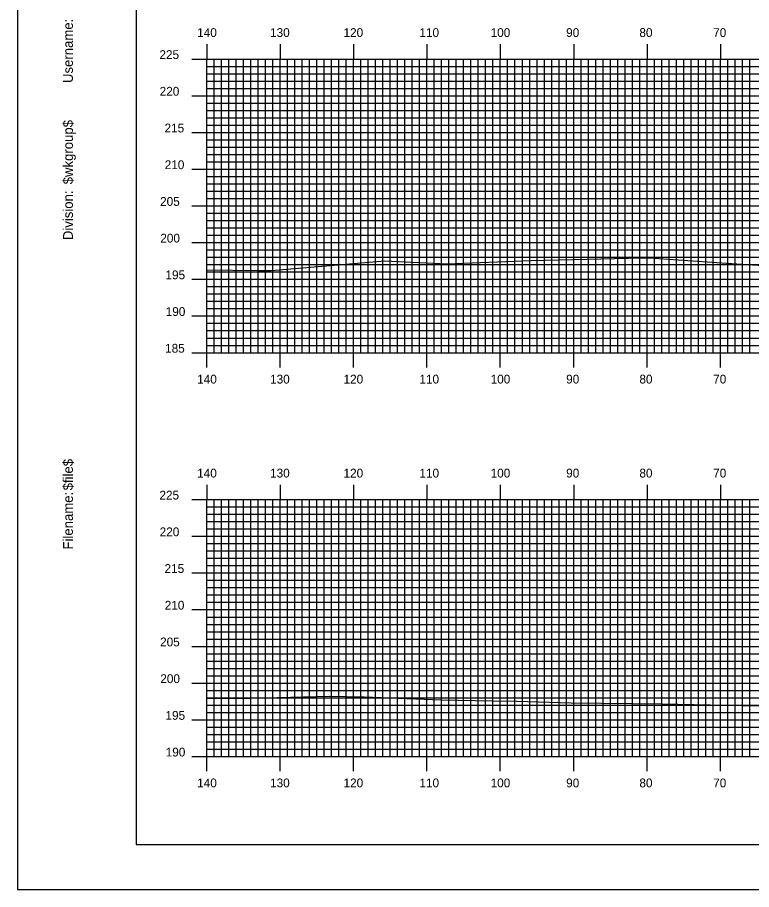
# Model space of a CAD drawing. Extents: x 1812161 to 1812504, y 442591 to 442811.
# Drawn here: x 1812160.6 to 1812260.7, y 442590.5 to 442709.3 of the extents above; entities that cross this region are included whole.
import ezdxf

# ---------------------------------------------------------------- set-up
doc = ezdxf.new("R2010")
doc.units = 0
for name, color, linetype in [('BORDER', 7, 'Continuous'), ('H_V ANNOTATION', 7, 'Continuous'), ('MAJOR', 7, 'Continuous'), ('MINOR', 7, 'Continuous'), ('PLOT BOUNDARY', 7, 'Continuous'), ('S_Roadway_Centerline', 7, 'Continuous')]:
    doc.layers.add(name, color=color, linetype=linetype)

msp = doc.modelspace()

# ---------------------------------------------------------------- linework, layer by layer
at = {"layer": 'BORDER'}
msp.add_lwpolyline([(1812176.83, 442596.67), (1812496.83, 442596.67), (1812496.83, 442806.67), (1812176.83, 442806.67)], close=True, dxfattribs=at)
at = {"layer": 'MAJOR'}
for p, q in [((1812186.43, 442705.67), (1812186.43, 442703.67)), ((1812196.43, 442705.67), (1812196.43, 442703.67)), ((1812206.43, 442705.67), (1812206.43, 442703.67)), ((1812216.43, 442705.67), (1812216.43, 442703.67)), ((1812226.43, 442705.67), (1812226.43, 442703.67)), ((1812236.43, 442705.67), (1812236.43, 442703.67)), ((1812246.43, 442705.67), (1812246.43, 442703.67)), ((1812256.43, 442705.67), (1812256.43, 442703.67)), ((1812184.42, 442703.67), (1812186.43, 442703.67)), ((1812186.43, 442703.67), (1812466.43, 442703.67)), ((1812186.43, 442663.67), (1812186.43, 442703.67)), ((1812186.43, 442663.67), (1812186.43, 442703.67)), ((1812186.43, 442703.67), (1812466.43, 442703.67)), ((1812196.43, 442663.67), (1812196.43, 442703.67)), ((1812206.43, 442663.67), (1812206.43, 442703.67)), ((1812216.43, 442663.67), (1812216.43, 442703.67)), ((1812226.43, 442663.67), (1812226.43, 442703.67)), ((1812236.43, 442663.67), (1812236.43, 442703.67)), ((1812246.43, 442663.67), (1812246.43, 442703.67)), ((1812256.43, 442663.67), (1812256.43, 442703.67)), ((1812184.42, 442698.67), (1812186.43, 442698.67)), ((1812186.43, 442698.67), (1812466.43, 442698.67)), ((1812184.42, 442693.67), (1812186.43, 442693.67)), ((1812186.43, 442693.67), (1812466.43, 442693.67)), ((1812184.42, 442688.67), (1812186.43, 442688.67)), ((1812186.43, 442688.67), (1812466.43, 442688.67)), ((1812184.42, 442683.67), (1812186.43, 442683.67)), ((1812186.43, 442683.67), (1812466.43, 442683.67)), ((1812184.42, 442678.67), (1812186.43, 442678.67)), ((1812186.43, 442678.67), (1812466.43, 442678.67)), ((1812184.42, 442673.67), (1812186.43, 442673.67)), ((1812186.43, 442673.67), (1812466.43, 442673.67)), ((1812184.42, 442668.67), (1812186.43, 442668.67)), ((1812186.43, 442668.67), (1812466.43, 442668.67)), ((1812184.42, 442663.67), (1812186.43, 442663.67)), ((1812186.43, 442663.67), (1812466.43, 442663.67)), ((1812186.43, 442663.67), (1812466.43, 442663.67)), ((1812186.43, 442661.66), (1812186.43, 442663.67)), ((1812196.43, 442661.66), (1812196.43, 442663.67)), ((1812206.43, 442661.66), (1812206.43, 442663.67)), ((1812216.43, 442661.66), (1812216.43, 442663.67)), ((1812226.43, 442661.66), (1812226.43, 442663.67)), ((1812236.43, 442661.66), (1812236.43, 442663.67)), ((1812246.43, 442661.66), (1812246.43, 442663.67)), ((1812256.43, 442661.66), (1812256.43, 442663.67)), ((1812186.43, 442645.67), (1812186.43, 442643.67)), ((1812196.43, 442645.67), (1812196.43, 442643.67)), ((1812206.43, 442645.67), (1812206.43, 442643.67)), ((1812216.43, 442645.67), (1812216.43, 442643.67)), ((1812226.43, 442645.67), (1812226.43, 442643.67)), ((1812236.43, 442645.67), (1812236.43, 442643.67)), ((1812246.43, 442645.67), (1812246.43, 442643.67)), ((1812256.43, 442645.67), (1812256.43, 442643.67)), ((1812184.42, 442643.67), (1812186.43, 442643.67)), ((1812186.43, 442643.67), (1812466.43, 442643.67)), ((1812186.43, 442608.67), (1812186.43, 442643.67)), ((1812186.43, 442608.67), (1812186.43, 442643.67)), ((1812186.43, 442643.67), (1812466.43, 442643.67)), ((1812196.43, 442608.67), (1812196.43, 442643.67)), ((1812206.43, 442608.67), (1812206.43, 442643.67)), ((1812216.43, 442608.67), (1812216.43, 442643.67)), ((1812226.43, 442608.67), (1812226.43, 442643.67)), ((1812236.43, 442608.67), (1812236.43, 442643.67)), ((1812246.43, 442608.67), (1812246.43, 442643.67)), ((1812256.43, 442608.67), (1812256.43, 442643.67)), ((1812184.42, 442638.67), (1812186.43, 442638.67)), ((1812186.43, 442638.67), (1812466.43, 442638.67)), ((1812184.42, 442633.67), (1812186.43, 442633.67)), ((1812186.43, 442633.67), (1812466.43, 442633.67)), ((1812184.42, 442628.67), (1812186.43, 442628.67)), ((1812186.43, 442628.67), (1812466.43, 442628.67)), ((1812184.42, 442623.67), (1812186.43, 442623.67)), ((1812186.43, 442623.67), (1812466.43, 442623.67)), ((1812184.42, 442618.67), (1812186.43, 442618.67)), ((1812186.43, 442618.67), (1812466.43, 442618.67)), ((1812184.42, 442613.67), (1812186.43, 442613.67)), ((1812186.43, 442613.67), (1812466.43, 442613.67)), ((1812184.42, 442608.67), (1812186.43, 442608.67)), ((1812186.43, 442608.67), (1812466.43, 442608.67)), ((1812186.43, 442608.67), (1812466.43, 442608.67)), ((1812186.43, 442606.66), (1812186.43, 442608.67)), ((1812196.43, 442606.66), (1812196.43, 442608.67)), ((1812206.43, 442606.66), (1812206.43, 442608.67)), ((1812216.43, 442606.66), (1812216.43, 442608.67)), ((1812226.43, 442606.66), (1812226.43, 442608.67)), ((1812236.43, 442606.66), (1812236.43, 442608.67)), ((1812246.43, 442606.66), (1812246.43, 442608.67)), ((1812256.43, 442606.66), (1812256.43, 442608.67))]:
    msp.add_line(p, q, dxfattribs=at)
at = {"layer": 'MINOR'}
for p, q in [((1812186.43, 442702.67), (1812466.43, 442702.67)), ((1812186.43, 442702.67), (1812188.43, 442702.67)), ((1812187.43, 442663.67), (1812187.43, 442703.67)), ((1812188.43, 442663.67), (1812188.43, 442703.67)), ((1812189.43, 442663.67), (1812189.43, 442703.67)), ((1812190.43, 442663.67), (1812190.43, 442703.67)), ((1812191.43, 442663.67), (1812191.43, 442703.67)), ((1812192.43, 442663.67), (1812192.43, 442703.67)), ((1812193.43, 442663.67), (1812193.43, 442703.67)), ((1812194.43, 442663.67), (1812194.43, 442703.67)), ((1812195.43, 442663.67), (1812195.43, 442703.67)), ((1812197.43, 442663.67), (1812197.43, 442703.67)), ((1812198.43, 442663.67), (1812198.43, 442703.67)), ((1812199.43, 442663.67), (1812199.43, 442703.67)), ((1812200.43, 442663.67), (1812200.43, 442703.67)), ((1812201.43, 442663.67), (1812201.43, 442703.67)), ((1812202.43, 442663.67), (1812202.43, 442703.67)), ((1812203.43, 442663.67), (1812203.43, 442703.67)), ((1812204.43, 442663.67), (1812204.43, 442703.67)), ((1812205.43, 442663.67), (1812205.43, 442703.67)), ((1812207.43, 442663.67), (1812207.43, 442703.67)), ((1812208.43, 442663.67), (1812208.43, 442703.67)), ((1812209.43, 442663.67), (1812209.43, 442703.67)), ((1812210.43, 442663.67), (1812210.43, 442703.67)), ((1812211.43, 442663.67), (1812211.43, 442703.67)), ((1812212.43, 442663.67), (1812212.43, 442703.67)), ((1812213.43, 442663.67), (1812213.43, 442703.67)), ((1812214.43, 442663.67), (1812214.43, 442703.67)), ((1812215.43, 442663.67), (1812215.43, 442703.67)), ((1812217.43, 442663.67), (1812217.43, 442703.67)), ((1812218.43, 442663.67), (1812218.43, 442703.67)), ((1812219.43, 442663.67), (1812219.43, 442703.67)), ((1812220.43, 442663.67), (1812220.43, 442703.67)), ((1812221.43, 442663.67), (1812221.43, 442703.67)), ((1812222.43, 442663.67), (1812222.43, 442703.67)), ((1812223.43, 442663.67), (1812223.43, 442703.67)), ((1812224.43, 442663.67), (1812224.43, 442703.67)), ((1812225.43, 442663.67), (1812225.43, 442703.67)), ((1812227.43, 442663.67), (1812227.43, 442703.67)), ((1812228.43, 442663.67), (1812228.43, 442703.67)), ((1812229.43, 442663.67), (1812229.43, 442703.67)), ((1812230.43, 442663.67), (1812230.43, 442703.67)), ((1812231.43, 442663.67), (1812231.43, 442703.67)), ((1812232.43, 442663.67), (1812232.43, 442703.67)), ((1812233.43, 442663.67), (1812233.43, 442703.67)), ((1812234.43, 442663.67), (1812234.43, 442703.67)), ((1812235.43, 442663.67), (1812235.43, 442703.67)), ((1812237.43, 442663.67), (1812237.43, 442703.67)), ((1812238.43, 442663.67), (1812238.43, 442703.67)), ((1812239.43, 442663.67), (1812239.43, 442703.67)), ((1812240.43, 442663.67), (1812240.43, 442703.67)), ((1812241.43, 442663.67), (1812241.43, 442703.67)), ((1812242.43, 442663.67), (1812242.43, 442703.67)), ((1812243.43, 442663.67), (1812243.43, 442703.67)), ((1812244.43, 442663.67), (1812244.43, 442703.67)), ((1812245.43, 442663.67), (1812245.43, 442703.67)), ((1812247.43, 442663.67), (1812247.43, 442703.67)), ((1812248.43, 442663.67), (1812248.43, 442703.67)), ((1812249.43, 442663.67), (1812249.43, 442703.67)), ((1812250.43, 442663.67), (1812250.43, 442703.67)), ((1812251.43, 442663.67), (1812251.43, 442703.67)), ((1812252.43, 442663.67), (1812252.43, 442703.67)), ((1812253.43, 442663.67), (1812253.43, 442703.67)), ((1812254.43, 442663.67), (1812254.43, 442703.67)), ((1812255.43, 442663.67), (1812255.43, 442703.67)), ((1812257.43, 442663.67), (1812257.43, 442703.67)), ((1812258.43, 442663.67), (1812258.43, 442703.67)), ((1812259.43, 442663.67), (1812259.43, 442703.67)), ((1812260.43, 442663.67), (1812260.43, 442703.67)), ((1812186.43, 442701.67), (1812466.43, 442701.67)), ((1812186.43, 442701.67), (1812188.43, 442701.67)), ((1812186.43, 442700.67), (1812466.43, 442700.67)), ((1812186.43, 442700.67), (1812188.43, 442700.67)), ((1812186.43, 442699.67), (1812466.43, 442699.67)), ((1812186.43, 442699.67), (1812188.43, 442699.67)), ((1812186.43, 442697.67), (1812466.43, 442697.67)), ((1812186.43, 442697.67), (1812188.43, 442697.67)), ((1812186.43, 442696.67), (1812466.43, 442696.67)), ((1812186.43, 442696.67), (1812188.43, 442696.67)), ((1812186.43, 442695.67), (1812466.43, 442695.67)), ((1812186.43, 442695.67), (1812188.43, 442695.67)), ((1812186.43, 442694.67), (1812466.43, 442694.67)), ((1812186.43, 442694.67), (1812188.43, 442694.67)), ((1812186.43, 442692.67), (1812466.43, 442692.67)), ((1812186.43, 442692.67), (1812188.43, 442692.67)), ((1812186.43, 442691.67), (1812466.43, 442691.67)), ((1812186.43, 442691.67), (1812188.43, 442691.67)), ((1812186.43, 442690.67), (1812466.43, 442690.67)), ((1812186.43, 442690.67), (1812188.43, 442690.67)), ((1812186.43, 442689.67), (1812466.43, 442689.67)), ((1812186.43, 442689.67), (1812188.43, 442689.67)), ((1812186.43, 442687.67), (1812466.43, 442687.67)), ((1812186.43, 442687.67), (1812188.43, 442687.67)), ((1812186.43, 442686.67), (1812466.43, 442686.67)), ((1812186.43, 442686.67), (1812188.43, 442686.67)), ((1812186.43, 442685.67), (1812466.43, 442685.67)), ((1812186.43, 442685.67), (1812188.43, 442685.67)), ((1812186.43, 442684.67), (1812466.43, 442684.67)), ((1812186.43, 442684.67), (1812188.43, 442684.67)), ((1812186.43, 442682.67), (1812466.43, 442682.67)), ((1812186.43, 442682.67), (1812188.43, 442682.67)), ((1812186.43, 442681.67), (1812466.43, 442681.67)), ((1812186.43, 442681.67), (1812188.43, 442681.67)), ((1812186.43, 442680.67), (1812466.43, 442680.67)), ((1812186.43, 442680.67), (1812188.43, 442680.67)), ((1812186.43, 442679.67), (1812466.43, 442679.67)), ((1812186.43, 442679.67), (1812188.43, 442679.67)), ((1812186.43, 442677.67), (1812466.43, 442677.67)), ((1812186.43, 442677.67), (1812188.43, 442677.67)), ((1812186.43, 442676.67), (1812466.43, 442676.67)), ((1812186.43, 442676.67), (1812188.43, 442676.67)), ((1812186.43, 442675.67), (1812466.43, 442675.67)), ((1812186.43, 442675.67), (1812188.43, 442675.67)), ((1812186.43, 442674.67), (1812466.43, 442674.67)), ((1812186.43, 442674.67), (1812188.43, 442674.67)), ((1812186.43, 442672.67), (1812466.43, 442672.67)), ((1812186.43, 442672.67), (1812188.43, 442672.67)), ((1812186.43, 442671.67), (1812466.43, 442671.67)), ((1812186.43, 442671.67), (1812188.43, 442671.67)), ((1812186.43, 442670.67), (1812466.43, 442670.67)), ((1812186.43, 442670.67), (1812188.43, 442670.67)), ((1812186.43, 442669.67), (1812466.43, 442669.67)), ((1812186.43, 442669.67), (1812188.43, 442669.67)), ((1812186.43, 442667.67), (1812466.43, 442667.67)), ((1812186.43, 442667.67), (1812188.43, 442667.67)), ((1812186.43, 442666.67), (1812466.43, 442666.67)), ((1812186.43, 442666.67), (1812188.43, 442666.67)), ((1812186.43, 442665.67), (1812466.43, 442665.67)), ((1812186.43, 442665.67), (1812188.43, 442665.67)), ((1812186.43, 442664.67), (1812466.43, 442664.67)), ((1812186.43, 442664.67), (1812188.43, 442664.67)), ((1812187.43, 442608.67), (1812187.43, 442643.67)), ((1812188.43, 442608.67), (1812188.43, 442643.67)), ((1812189.43, 442608.67), (1812189.43, 442643.67)), ((1812190.43, 442608.67), (1812190.43, 442643.67)), ((1812191.43, 442608.67), (1812191.43, 442643.67)), ((1812192.43, 442608.67), (1812192.43, 442643.67)), ((1812193.43, 442608.67), (1812193.43, 442643.67)), ((1812194.43, 442608.67), (1812194.43, 442643.67)), ((1812195.43, 442608.67), (1812195.43, 442643.67)), ((1812197.43, 442608.67), (1812197.43, 442643.67)), ((1812198.43, 442608.67), (1812198.43, 442643.67)), ((1812199.43, 442608.67), (1812199.43, 442643.67)), ((1812200.43, 442608.67), (1812200.43, 442643.67)), ((1812201.43, 442608.67), (1812201.43, 442643.67)), ((1812202.43, 442608.67), (1812202.43, 442643.67)), ((1812203.43, 442608.67), (1812203.43, 442643.67)), ((1812204.43, 442608.67), (1812204.43, 442643.67)), ((1812205.43, 442608.67), (1812205.43, 442643.67)), ((1812207.43, 442608.67), (1812207.43, 442643.67)), ((1812208.43, 442608.67), (1812208.43, 442643.67)), ((1812209.43, 442608.67), (1812209.43, 442643.67)), ((1812210.43, 442608.67), (1812210.43, 442643.67)), ((1812211.43, 442608.67), (1812211.43, 442643.67)), ((1812212.43, 442608.67), (1812212.43, 442643.67)), ((1812213.43, 442608.67), (1812213.43, 442643.67)), ((1812214.43, 442608.67), (1812214.43, 442643.67)), ((1812215.43, 442608.67), (1812215.43, 442643.67)), ((1812217.43, 442608.67), (1812217.43, 442643.67)), ((1812218.43, 442608.67), (1812218.43, 442643.67)), ((1812219.43, 442608.67), (1812219.43, 442643.67)), ((1812220.43, 442608.67), (1812220.43, 442643.67)), ((1812221.43, 442608.67), (1812221.43, 442643.67)), ((1812222.43, 442608.67), (1812222.43, 442643.67)), ((1812223.43, 442608.67), (1812223.43, 442643.67)), ((1812224.43, 442608.67), (1812224.43, 442643.67)), ((1812225.43, 442608.67), (1812225.43, 442643.67)), ((1812227.43, 442608.67), (1812227.43, 442643.67)), ((1812228.43, 442608.67), (1812228.43, 442643.67)), ((1812229.43, 442608.67), (1812229.43, 442643.67)), ((1812230.43, 442608.67), (1812230.43, 442643.67)), ((1812231.43, 442608.67), (1812231.43, 442643.67)), ((1812232.43, 442608.67), (1812232.43, 442643.67)), ((1812233.43, 442608.67), (1812233.43, 442643.67)), ((1812234.43, 442608.67), (1812234.43, 442643.67)), ((1812235.43, 442608.67), (1812235.43, 442643.67)), ((1812237.43, 442608.67), (1812237.43, 442643.67)), ((1812238.43, 442608.67), (1812238.43, 442643.67)), ((1812239.43, 442608.67), (1812239.43, 442643.67)), ((1812240.43, 442608.67), (1812240.43, 442643.67)), ((1812241.43, 442608.67), (1812241.43, 442643.67)), ((1812242.43, 442608.67), (1812242.43, 442643.67)), ((1812243.43, 442608.67), (1812243.43, 442643.67)), ((1812244.43, 442608.67), (1812244.43, 442643.67)), ((1812245.43, 442608.67), (1812245.43, 442643.67)), ((1812247.43, 442608.67), (1812247.43, 442643.67)), ((1812248.43, 442608.67), (1812248.43, 442643.67)), ((1812249.43, 442608.67), (1812249.43, 442643.67)), ((1812250.43, 442608.67), (1812250.43, 442643.67)), ((1812251.43, 442608.67), (1812251.43, 442643.67)), ((1812252.43, 442608.67), (1812252.43, 442643.67)), ((1812253.43, 442608.67), (1812253.43, 442643.67)), ((1812254.43, 442608.67), (1812254.43, 442643.67)), ((1812255.43, 442608.67), (1812255.43, 442643.67)), ((1812257.43, 442608.67), (1812257.43, 442643.67)), ((1812258.43, 442608.67), (1812258.43, 442643.67)), ((1812259.43, 442608.67), (1812259.43, 442643.67)), ((1812260.43, 442608.67), (1812260.43, 442643.67)), ((1812186.43, 442642.67), (1812466.43, 442642.67)), ((1812186.43, 442642.67), (1812188.43, 442642.67)), ((1812186.43, 442641.67), (1812466.43, 442641.67)), ((1812186.43, 442641.67), (1812188.43, 442641.67)), ((1812186.43, 442640.67), (1812466.43, 442640.67)), ((1812186.43, 442640.67), (1812188.43, 442640.67)), ((1812186.43, 442639.67), (1812466.43, 442639.67)), ((1812186.43, 442639.67), (1812188.43, 442639.67)), ((1812186.43, 442637.67), (1812466.43, 442637.67)), ((1812186.43, 442637.67), (1812188.43, 442637.67)), ((1812186.43, 442636.67), (1812466.43, 442636.67)), ((1812186.43, 442636.67), (1812188.43, 442636.67)), ((1812186.43, 442635.67), (1812466.43, 442635.67)), ((1812186.43, 442635.67), (1812188.43, 442635.67)), ((1812186.43, 442634.67), (1812466.43, 442634.67)), ((1812186.43, 442634.67), (1812188.43, 442634.67)), ((1812186.43, 442632.67), (1812466.43, 442632.67)), ((1812186.43, 442632.67), (1812188.43, 442632.67)), ((1812186.43, 442631.67), (1812466.43, 442631.67)), ((1812186.43, 442631.67), (1812188.43, 442631.67)), ((1812186.43, 442630.67), (1812466.43, 442630.67)), ((1812186.43, 442630.67), (1812188.43, 442630.67)), ((1812186.43, 442629.67), (1812466.43, 442629.67)), ((1812186.43, 442629.67), (1812188.43, 442629.67)), ((1812186.43, 442627.67), (1812466.43, 442627.67)), ((1812186.43, 442627.67), (1812188.43, 442627.67)), ((1812186.43, 442626.67), (1812466.43, 442626.67)), ((1812186.43, 442626.67), (1812188.43, 442626.67)), ((1812186.43, 442625.67), (1812466.43, 442625.67)), ((1812186.43, 442625.67), (1812188.43, 442625.67)), ((1812186.43, 442624.67), (1812466.43, 442624.67)), ((1812186.43, 442624.67), (1812188.43, 442624.67)), ((1812186.43, 442622.67), (1812466.43, 442622.67)), ((1812186.43, 442622.67), (1812188.43, 442622.67)), ((1812186.43, 442621.67), (1812466.43, 442621.67)), ((1812186.43, 442621.67), (1812188.43, 442621.67)), ((1812186.43, 442620.67), (1812466.43, 442620.67)), ((1812186.43, 442620.67), (1812188.43, 442620.67)), ((1812186.43, 442619.67), (1812466.43, 442619.67)), ((1812186.43, 442619.67), (1812188.43, 442619.67)), ((1812186.43, 442617.67), (1812466.43, 442617.67)), ((1812186.43, 442617.67), (1812188.43, 442617.67)), ((1812186.43, 442616.67), (1812466.43, 442616.67)), ((1812186.43, 442616.67), (1812188.43, 442616.67)), ((1812186.43, 442615.67), (1812466.43, 442615.67)), ((1812186.43, 442615.67), (1812188.43, 442615.67)), ((1812186.43, 442614.67), (1812466.43, 442614.67)), ((1812186.43, 442614.67), (1812188.43, 442614.67)), ((1812186.43, 442612.67), (1812466.43, 442612.67)), ((1812186.43, 442612.67), (1812188.43, 442612.67)), ((1812186.43, 442611.67), (1812466.43, 442611.67)), ((1812186.43, 442611.67), (1812188.43, 442611.67)), ((1812186.43, 442610.67), (1812466.43, 442610.67)), ((1812186.43, 442610.67), (1812188.43, 442610.67)), ((1812186.43, 442609.67), (1812466.43, 442609.67)), ((1812186.43, 442609.67), (1812188.43, 442609.67))]:
    msp.add_line(p, q, dxfattribs=at)
at = {"layer": 'PLOT BOUNDARY'}
msp.add_lwpolyline([(1812160.64, 442590.55), (1812500.64, 442590.55), (1812500.64, 442810.55), (1812160.64, 442810.55)], close=True, dxfattribs=at)
at = {"layer": 'S_Roadway_Centerline'}
for points in [[(1812186.43, 442674.96), (1812193.49, 442674.87), (1812194.41, 442674.88), (1812195.23, 442674.88), (1812210.71, 442676.18), (1812219.13, 442675.79), (1812230.64, 442676.24), (1812243.89, 442676.54), (1812246.7, 442676.6), (1812257.26, 442675.86), (1812265.07, 442675.35), (1812269.05, 442675.38), (1812278.98, 442675.22), (1812294.55, 442675.24), (1812315.55, 442675.14), (1812318.24, 442675.16), (1812319.32, 442675.14), (1812336.42, 442674.72), (1812344.7, 442674.69), (1812354.49, 442674.44), (1812363.29, 442674.11), (1812371.95, 442674.39), (1812382.38, 442674.43), (1812389.75, 442673.94)], [(1812186.43, 442616.63), (1812188.43, 442616.56), (1812189.12, 442616.61), (1812190.7, 442616.57), (1812203.16, 442616.87), (1812207.87, 442616.81), (1812218.37, 442616.37), (1812225.32, 442616.27), (1812228.69, 442616.2), (1812236.1, 442615.96), (1812248.45, 442615.83), (1812261.63, 442615.57)]]:
    msp.add_lwpolyline(points, dxfattribs=at)

# ---------------------------------------------------------------- texts
at = {"layer": 'BORDER'}
for s, p in [('Username:', (1812168.2, 442700.4)), ('$wkgroup$', (1812168.2, 442686.6)), ('Division:', (1812168.2, 442679)), ('$file$', (1812168.2, 442644.92)), ('Filename:', (1812168.2, 442636.86))]:
    msp.add_text(s, height=1.339, rotation=90, dxfattribs=at).set_placement(p)
at = {"layer": 'H_V ANNOTATION'}
for s, p in [('140', (1812185.13, 442706.67)), ('130', (1812195.06, 442706.67)), ('120', (1812205.07, 442706.67)), ('110', (1812215.41, 442706.67)), ('100', (1812225.11, 442706.67)), ('90', (1812235.4, 442706.67)), ('80', (1812245.38, 442706.67)), ('70', (1812255.43, 442706.67)), ('225', (1812179.99, 442703.67)), ('220', (1812180.02, 442698.67)), ('215', (1812180.68, 442693.67)), ('210', (1812180.71, 442688.67)), ('205', (1812180.08, 442683.67)), ('200', (1812180.11, 442678.67)), ('195', (1812180.81, 442673.67)), ('190', (1812180.84, 442668.67)), ('185', (1812180.76, 442663.67)), ('140', (1812185.13, 442659.47)), ('130', (1812195.06, 442659.47)), ('120', (1812205.07, 442659.47)), ('110', (1812215.41, 442659.47)), ('100', (1812225.11, 442659.47)), ('90', (1812235.4, 442659.47)), ('80', (1812245.38, 442659.47)), ('70', (1812255.43, 442659.47)), ('140', (1812185.13, 442646.67)), ('130', (1812195.06, 442646.67)), ('120', (1812205.07, 442646.67)), ('110', (1812215.41, 442646.67)), ('100', (1812225.11, 442646.67)), ('90', (1812235.4, 442646.67)), ('80', (1812245.38, 442646.67)), ('70', (1812255.43, 442646.67)), ('225', (1812179.99, 442643.67)), ('220', (1812180.02, 442638.67)), ('215', (1812180.68, 442633.67)), ('210', (1812180.71, 442628.67)), ('205', (1812180.08, 442623.67)), ('200', (1812180.11, 442618.67)), ('195', (1812180.81, 442613.67)), ('190', (1812180.84, 442608.67)), ('140', (1812185.13, 442604.47)), ('130', (1812195.06, 442604.47)), ('120', (1812205.07, 442604.47)), ('110', (1812215.41, 442604.47)), ('100', (1812225.11, 442604.47)), ('90', (1812235.4, 442604.47)), ('80', (1812245.38, 442604.47)), ('70', (1812255.43, 442604.47))]:
    msp.add_text(s, height=1.2, dxfattribs=at).set_placement(p)
at = {"layer": 'MAJOR'}
for p in [(1812186.42, 442663.67), (1812186.42, 442608.67)]:
    msp.add_text('-', height=0.012, dxfattribs=at).set_placement(p)

doc.saveas('drawing.dxf')
